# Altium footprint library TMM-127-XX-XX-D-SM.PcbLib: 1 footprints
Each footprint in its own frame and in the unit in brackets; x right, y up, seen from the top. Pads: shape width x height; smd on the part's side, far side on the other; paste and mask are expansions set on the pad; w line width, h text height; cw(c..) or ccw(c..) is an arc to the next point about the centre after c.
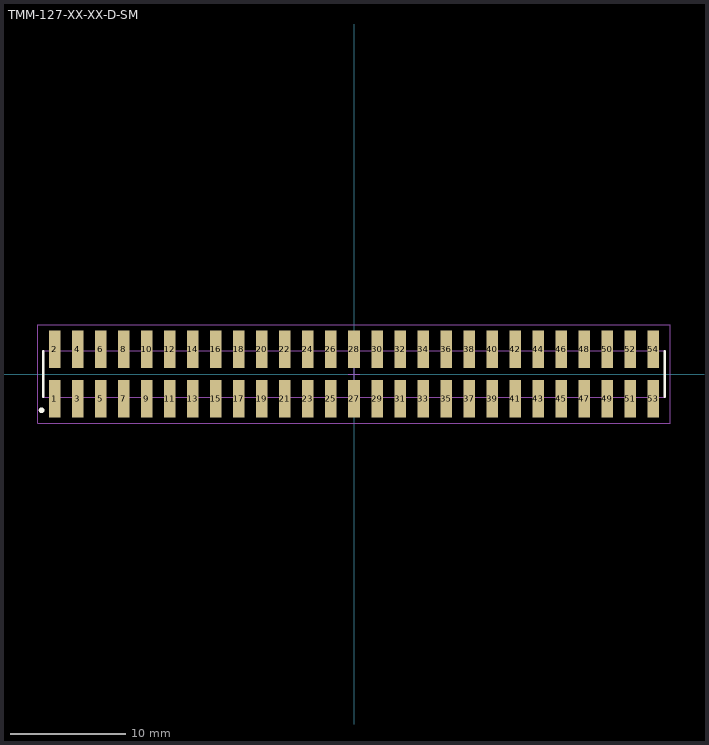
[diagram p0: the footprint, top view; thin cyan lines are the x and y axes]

## TMM-127-XX-XX-D-SM [mm] "2.00mm pitch, 54 pin, terminal strip; double row, SMT"
height 2.77
pads (54):
  rect 1x3.3 smd mask+0: 1(-26,-2.15) 2(-26,2.15) 3(-24,-2.15) 4(-24,2.15) 5(-22,-2.15) 6(-22,2.15) 7(-20,-2.15) 8(-20,2.15) 9(-18,-2.15) 10(-18,2.15) 11(-16,-2.15) 12(-16,2.15) 13(-14,-2.15) 14(-14,2.15) 15(-12,-2.15) 16(-12,2.15) 17(-10,-2.15) 18(-10,2.15) 19(-8,-2.15) 20(-8,2.15) 21(-6,-2.15) 22(-6,2.15) 23(-4,-2.15) 24(-4,2.15) 25(-2,-2.15) 26(-2,2.15) 27(0,-2.15) 28(0,2.15) 29(2,-2.15) 30(2,2.15) 31(4,-2.15) 32(4,2.15) 33(6,-2.15) 34(6,2.15) 35(8,-2.15) 36(8,2.15) 37(10,-2.15) 38(10,2.15) 39(12,-2.15) 40(12,2.15) 41(14,-2.15) 42(14,2.15) 43(16,-2.15) 44(16,2.15) 45(18,-2.15) 46(18,2.15) 47(20,-2.15) 48(20,2.15) 49(22,-2.15) 50(22,2.15) 51(24,-2.15) 52(24,2.15) 53(26,-2.15) 54(26,2.15)
Top Overlay:
  circle w0.25: c-27.15,-3.15 r0.125
  lines w0.2: -27,-2 -27,2 ; 27,-2 27,2
Mechanical 12:
  lines w0.001: -27,-2 -27,2 27,2 27,-2 -27,-2
Mechanical 13:
  lines w0.1: -27,-2 -27,2 27,2 27,-2 -27,-2
  text ".Designator" at 0,-0.127 h1.52
Mechanical 15:
  lines w0.05: -0.5,0 0.5,0 ; 0,-0.5 0,0.5 ; -27.5,-4.3 -27.5,4.3 27.5,4.3 27.5,-4.3 -27.5,-4.3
